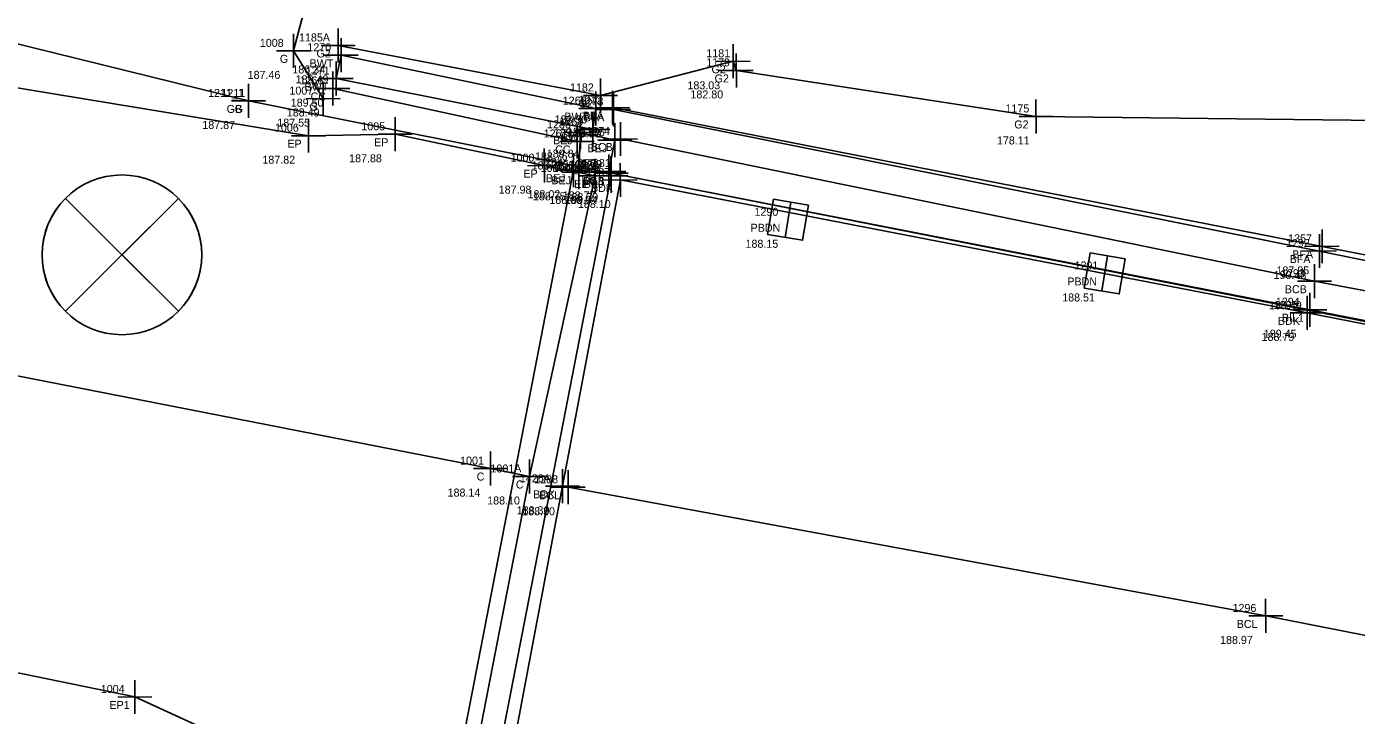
# Model space of a CAD drawing. Extents: x 1157913 to 1159198, y 600595 to 601244.
# Drawn here: x 1158460.89 to 1158510.75, y 600928.57 to 600954.39 of the extents above; entities that cross this region are included whole.
import ezdxf

# ---------------------------------------------------------------- set-up
doc = ezdxf.new("R2010")
doc.units = 0
for name, color, linetype in [('Default', 7, 'Continuous'), ('S_BoringLocation_AsDrilled', 7, 'Continuous'), ('S_Bridge_Centerline', 7, 'Continuous'), ('S_Bridge_Curb', 7, 'Continuous'), ('S_Bridge_Deck', 7, 'Continuous'), ('S_Bridge_Downspout', 7, 'Continuous'), ('S_Bridge_ExpansionJoint', 7, 'Continuous'), ('S_Bridge_Fascia', 7, 'Continuous'), ('S_Bridge_Rail', 7, 'Continuous'), ('S_Bridge_Wingwall', 7, 'Continuous'), ('S_Curb_Type_2', 7, 'Continuous'), ('S_Field_Code', 7, 'Continuous'), ('S_Ground_Elevation', 7, 'Continuous'), ('S_Ground_LevelString', 7, 'Continuous'), ('S_Guardrail_Beam', 7, 'Continuous'), ('S_Point_Elevation', 7, 'Continuous'), ('S_Point_Name', 7, 'Continuous'), ('S_Roadway_Centerline', 7, 'Continuous'), ('S_Roadway_Edge_Pavement', 7, 'Continuous'), ('S_Survey_Shot', 7, 'Continuous')]:
    doc.layers.add(name, color=color, linetype=linetype)

msp = doc.modelspace()

# ---------------------------------------------------------------- linework, layer by layer
at = {"layer": 'Default'}
for p, q in [((1158489.439, 600947.15), (1158489.439, 600947.15)), ((1158501.314, 600945.137), (1158501.314, 600945.137))]:
    msp.add_line(p, q, dxfattribs=at)
at = {"layer": 'S_BoringLocation_AsDrilled'}
for p, q in [((1158462.347, 600947.953), (1158466.581, 600943.719)), ((1158462.347, 600943.719), (1158466.581, 600947.953))]:
    msp.add_line(p, q, dxfattribs=at)
for points in [[(1158462.347, 600943.719), (1158464.464, 600945.836), (1158462.347, 600947.953)], [(1158466.581, 600947.953), (1158464.464, 600945.836), (1158466.581, 600943.719)]]:
    msp.add_lwpolyline(points, dxfattribs=at)
msp.add_circle((1158464.464, 600945.836), 2.994, dxfattribs=at)
for start, end in [(135, 225), (315, 45)]:
    msp.add_arc((1158464.464, 600945.836), 2.994, start, end, dxfattribs=at)
at = {"layer": 'S_Bridge_Centerline'}
msp.add_lwpolyline([(1158481.195, 600937.121), (1158507.351, 600932.296), (1158531.006, 600927.652), (1158554.323, 600923.112), (1158577.507, 600918.68), (1158601.407, 600914.027), (1158625.013, 600909.477), (1158647.737, 600904.925), (1158672.228, 600900.301), (1158696.593, 600895.817), (1158720.484, 600890.638)], dxfattribs=at)
at = {"layer": 'S_Bridge_Curb'}
msp.add_lwpolyline([(1158483.161, 600950.18), (1158509.184, 600944.847), (1158532.763, 600940.379), (1158556.45, 600935.563), (1158579.829, 600931.057), (1158603.376, 600926.445), (1158626.911, 600921.776), (1158650.768, 600917.187), (1158674.064, 600912.392), (1158697.671, 600908.06), (1158723.302, 600902.985)], dxfattribs=at)
at = {"layer": 'S_Bridge_Deck'}
msp.add_lwpolyline([(1158483.154, 600948.642), (1158508.91, 600943.661), (1158532.625, 600939.025), (1158556.015, 600934.45), (1158579.602, 600929.788), (1158603.216, 600925.172), (1158626.871, 600920.52), (1158650.274, 600915.846), (1158673.938, 600911.396), (1158697.587, 600906.778), (1158722.887, 600901.626), (1158720.511, 600890.631), (1158717.86, 600878.361), (1158692.562, 600883.367), (1158669.405, 600887.913), (1158645.122, 600892.525), (1158622.108, 600897.299), (1158598.216, 600901.842), (1158574.819, 600906.519), (1158551.011, 600911.144), (1158527.523, 600915.567), (1158503.608, 600920.228), (1158478.738, 600925.244), (1158480.987, 600937.158)], close=True, dxfattribs=at)
at = {"layer": 'S_Bridge_Downspout'}
for p, q in [((1158489.549, 600947.807), (1158489.329, 600946.492)), ((1158501.424, 600945.795), (1158501.204, 600944.48))]:
    msp.add_line(p, q, dxfattribs=at)
for points in [[(1158488.891, 600947.917), (1158490.207, 600947.698), (1158489.987, 600946.382), (1158488.672, 600946.602)], [(1158500.766, 600945.905), (1158502.081, 600945.685), (1158501.862, 600944.37), (1158500.547, 600944.59)]]:
    msp.add_lwpolyline(points, close=True, dxfattribs=at)
at = {"layer": 'S_Bridge_ExpansionJoint'}
msp.add_lwpolyline([(1158482.951, 600950.133), (1158482.722, 600948.965), (1158482.812, 600948.797), (1158478.267, 600925.445), (1158478.173, 600925.283), (1158477.852, 600924.467), (1158476.579, 600924.608), (1158476.87, 600925.538), (1158476.863, 600925.631), (1158481.393, 600949.008), (1158481.599, 600948.931), (1158481.661, 600950.428)], close=True, dxfattribs=at)
at = {"layer": 'S_Bridge_Fascia'}
msp.add_lwpolyline([(1158482.861, 600951.354), (1158482.898, 600951.287), (1158509.367, 600945.979), (1158532.925, 600941.176), (1158556.366, 600936.562), (1158579.862, 600931.952), (1158603.5, 600927.221), (1158627.041, 600922.676), (1158650.576, 600918.007), (1158674.159, 600913.359), (1158697.787, 600908.797), (1158724.39, 600903.681), (1158724.298, 600904.075), (1158697.887, 600909.28), (1158674.374, 600913.874), (1158650.514, 600918.558), (1158627.158, 600923.073), (1158603.563, 600927.819), (1158579.96, 600932.392), (1158556.434, 600937.017), (1158532.882, 600941.581), (1158509.466, 600946.154)], close=True, dxfattribs=at)
at = {"layer": 'S_Bridge_Rail'}
msp.add_lwpolyline([(1158482.805, 600948.902), (1158509.002, 600943.778), (1158532.726, 600939.143), (1158579.85, 600929.84), (1158603.334, 600925.337), (1158626.819, 600920.746), (1158650.464, 600916.056), (1158674.206, 600911.454), (1158697.827, 600906.811), (1158723.142, 600901.903)], dxfattribs=at)
at = {"layer": 'S_Bridge_Wingwall'}
msp.add_lwpolyline([(1158482.119, 600950.531), (1158482.238, 600951.319), (1158472.688, 600953.318), (1158472.501, 600952.443)], close=True, dxfattribs=at)
at = {"layer": 'S_Curb_Type_2'}
msp.add_lwpolyline([(1158472.368, 600952.074), (1158481.537, 600950.087)], dxfattribs=at)
at = {"layer": 'S_Ground_Elevation'}
for points in [[(1158472.015, 600951.692), (1158470.903, 600953.484), (1158471.497, 600955.775), (1158438.857, 600962.856), (1158401.09, 600969.759), (1158355.506, 600978.983), (1158309.086, 600988.559), (1158285.714, 600993.001), (1158274.891, 600997.675), (1158269.917, 601000.901)], [(1158273.349, 600992.479), (1158301.688, 600987.714), (1158337.49, 600979.594), (1158372.463, 600972.765), (1158424.594, 600962.151), (1158447.246, 600957.035), (1158469.207, 600951.606)], [(1158513.787, 600950.853), (1158498.739, 600951.025), (1158487.502, 600952.75), (1158487.388, 600953.092), (1158482.406, 600951.812), (1158472.577, 600953.687)]]:
    msp.add_lwpolyline(points, dxfattribs=at)
at = {"layer": 'S_Ground_LevelString'}
msp.add_line((1158482.21, 600948.796), (1158482.21, 600948.796), dxfattribs=at)
for points in [[(1158482.21, 600948.796), (1158479.75, 600937.525)], [(1158477.417, 600925.559), (1158479.75, 600937.525)]]:
    msp.add_lwpolyline(points, dxfattribs=at)
at = {"layer": 'S_Guardrail_Beam'}
msp.add_lwpolyline([(1158300.685, 600990.749), (1158313.178, 600986.765), (1158323.044, 600983.483), (1158337.49, 600979.594), (1158372.463, 600972.765), (1158424.594, 600962.151), (1158447.246, 600957.035), (1158469.207, 600951.606), (1158482.805, 600948.902), (1158556.266, 600934.455)], dxfattribs=at)
at = {"layer": 'S_Roadway_Centerline'}
msp.add_lwpolyline([(1158479.75, 600937.525), (1158478.282, 600937.822), (1158436.668, 600945.983), (1158396.56, 600953.994), (1158354.467, 600962.235), (1158305.826, 600972.373), (1158264.305, 600980.659), (1158241.502, 600985.057), (1158213.717, 600990.543), (1158173.691, 600998.161), (1158140.3, 601004.996), (1158100.103, 601012.585), (1158058.41, 601021.086), (1158006.872, 601031.132), (1157981.56, 601036.209), (1157941.48, 601043.319), (1157939.696, 601043.817)], dxfattribs=at)
at = {"layer": 'S_Roadway_Edge_Pavement'}
for points in [[(1158482.21, 600948.796), (1158480.303, 600949.181), (1158474.708, 600950.356), (1158471.456, 600950.303), (1158438.531, 600955.721), (1158399.619, 600963.989), (1158355.02, 600972.94), (1158308.672, 600982.448), (1158275.006, 600989.351), (1158238.064, 600996.902), (1158217.026, 601000.576), (1158187.54, 601006.694), (1158142.453, 601015.564), (1158101.816, 601023.851), (1158061.148, 601031.765), (1158007.725, 601042.002), (1157989.546, 601045.447), (1157985.531, 601046.098), (1157938.913, 601055.56)], [(1158477.417, 600925.559), (1158475.969, 600925.8), (1158470.307, 600926.811), (1158464.953, 600929.258), (1158434.419, 600935.565), (1158394.467, 600943.733), (1158353.382, 600952.235), (1158303.702, 600962.318), (1158261.836, 600970.726), (1158252.612, 600972.631), (1158210.037, 600978.929), (1158172.668, 600988.59), (1158138.81, 600995.015), (1158098.517, 601002.533), (1158056.874, 601010.931), (1158005.398, 601020.726), (1157975.101, 601026.613), (1157952.322, 601030.415), (1157945.74, 601032.454), (1157914.88, 601038.54)]]:
    msp.add_lwpolyline(points, dxfattribs=at)
at = {"layer": 'S_Survey_Shot'}
for p, q in [((1158470.904, 600952.848), (1158470.902, 600954.12)), ((1158472.578, 600953.051), (1158472.575, 600954.324)), ((1158472.689, 600952.682), (1158472.686, 600953.954)), ((1158470.267, 600953.483), (1158471.539, 600953.485)), ((1158470.903, 600953.484), (1158470.903, 600953.484)), ((1158471.94, 600953.686), (1158473.213, 600953.689)), ((1158472.577, 600953.687), (1158472.577, 600953.687)), ((1158487.389, 600952.456), (1158487.387, 600953.729)), ((1158487.503, 600952.114), (1158487.5, 600953.387)), ((1158472.051, 600953.317), (1158473.324, 600953.319)), ((1158472.502, 600951.807), (1158472.499, 600953.079)), ((1158472.688, 600953.318), (1158472.688, 600953.318)), ((1158486.752, 600953.091), (1158488.024, 600953.094)), ((1158487.388, 600953.092), (1158487.388, 600953.092)), ((1158471.864, 600952.442), (1158473.137, 600952.444)), ((1158472.37, 600951.438), (1158472.367, 600952.71)), ((1158472.501, 600952.443), (1158472.501, 600952.443)), ((1158482.408, 600951.176), (1158482.405, 600952.448)), ((1158486.865, 600952.749), (1158488.138, 600952.752)), ((1158487.502, 600952.75), (1158487.502, 600952.75)), ((1158469.208, 600950.97), (1158469.205, 600952.242)), ((1158469.208, 600950.97), (1158469.205, 600952.242)), ((1158471.732, 600952.073), (1158473.005, 600952.075)), ((1158472.016, 600951.055), (1158472.013, 600952.328)), ((1158472.368, 600952.074), (1158472.368, 600952.074)), ((1158482.239, 600950.682), (1158482.237, 600951.955)), ((1158482.863, 600950.717), (1158482.86, 600951.99)), ((1158482.899, 600950.651), (1158482.896, 600951.923)), ((1158468.57, 600951.605), (1158469.843, 600951.607)), ((1158468.57, 600951.605), (1158469.843, 600951.607)), ((1158469.207, 600951.606), (1158469.207, 600951.606)), ((1158469.207, 600951.606), (1158469.207, 600951.606)), ((1158471.379, 600951.69), (1158472.651, 600951.693)), ((1158472.015, 600951.692), (1158472.015, 600951.692)), ((1158481.77, 600951.811), (1158483.042, 600951.813)), ((1158482.225, 600951.352), (1158483.497, 600951.355)), ((1158482.406, 600951.812), (1158482.406, 600951.812)), ((1158482.861, 600951.354), (1158482.861, 600951.354)), ((1158498.741, 600950.389), (1158498.738, 600951.662)), ((1158471.457, 600949.667), (1158471.455, 600950.939)), ((1158474.709, 600949.72), (1158474.707, 600950.992)), ((1158481.602, 600951.317), (1158482.874, 600951.32)), ((1158481.662, 600949.792), (1158481.66, 600951.064)), ((1158482.12, 600949.895), (1158482.118, 600951.168)), ((1158482.238, 600951.319), (1158482.238, 600951.319)), ((1158482.261, 600951.286), (1158483.534, 600951.288)), ((1158482.898, 600951.287), (1158482.898, 600951.287)), ((1158498.103, 600951.024), (1158499.376, 600951.027)), ((1158498.739, 600951.025), (1158498.739, 600951.025)), ((1158474.072, 600950.355), (1158475.344, 600950.357)), ((1158474.708, 600950.356), (1158474.708, 600950.356)), ((1158481.025, 600950.427), (1158482.297, 600950.43)), ((1158481.483, 600950.53), (1158482.755, 600950.533)), ((1158481.538, 600949.451), (1158481.536, 600950.723)), ((1158481.661, 600950.428), (1158481.661, 600950.428)), ((1158482.119, 600950.531), (1158482.119, 600950.531)), ((1158482.952, 600949.497), (1158482.95, 600950.77)), ((1158483.162, 600949.544), (1158483.16, 600950.816)), ((1158470.82, 600950.301), (1158472.092, 600950.304)), ((1158471.456, 600950.303), (1158471.456, 600950.303)), ((1158480.901, 600950.086), (1158482.173, 600950.088)), ((1158481.537, 600950.087), (1158481.537, 600950.087)), ((1158482.315, 600950.132), (1158483.587, 600950.135)), ((1158482.525, 600950.179), (1158483.797, 600950.181)), ((1158482.951, 600950.133), (1158482.951, 600950.133)), ((1158483.161, 600950.18), (1158483.161, 600950.18)), ((1158480.305, 600948.544), (1158480.302, 600949.817)), ((1158481.395, 600948.371), (1158481.392, 600949.644)), ((1158481.6, 600948.294), (1158481.597, 600949.567)), ((1158482.211, 600948.159), (1158482.209, 600949.432)), ((1158482.211, 600948.159), (1158482.209, 600949.432)), ((1158482.723, 600948.328), (1158482.72, 600949.601)), ((1158482.806, 600948.266), (1158482.803, 600949.538)), ((1158482.806, 600948.266), (1158482.803, 600949.538)), ((1158482.813, 600948.161), (1158482.81, 600949.433)), ((1158479.667, 600949.179), (1158480.939, 600949.182)), ((1158480.303, 600949.181), (1158480.303, 600949.181)), ((1158480.757, 600949.006), (1158482.03, 600949.009)), ((1158480.962, 600948.929), (1158482.235, 600948.932)), ((1158481.393, 600949.008), (1158481.393, 600949.008)), ((1158481.599, 600948.931), (1158481.599, 600948.931)), ((1158482.085, 600948.963), (1158483.358, 600948.966)), ((1158482.169, 600948.901), (1158483.441, 600948.903)), ((1158482.169, 600948.901), (1158483.441, 600948.903)), ((1158482.722, 600948.965), (1158482.722, 600948.965)), ((1158482.805, 600948.902), (1158482.805, 600948.902)), ((1158482.805, 600948.902), (1158482.805, 600948.902)), ((1158483.155, 600948.006), (1158483.152, 600949.278)), ((1158481.574, 600948.794), (1158482.846, 600948.797)), ((1158481.574, 600948.794), (1158482.846, 600948.797)), ((1158482.176, 600948.796), (1158483.448, 600948.798)), ((1158482.21, 600948.796), (1158482.21, 600948.796)), ((1158482.21, 600948.796), (1158482.21, 600948.796)), ((1158482.517, 600948.641), (1158483.79, 600948.643)), ((1158482.812, 600948.797), (1158482.812, 600948.797)), ((1158483.154, 600948.642), (1158483.154, 600948.642)), ((1158509.368, 600945.343), (1158509.366, 600946.615)), ((1158509.468, 600945.518), (1158509.465, 600946.791)), ((1158508.731, 600945.977), (1158510.003, 600945.98)), ((1158508.83, 600946.153), (1158510.103, 600946.156)), ((1158509.367, 600945.979), (1158509.367, 600945.979)), ((1158509.466, 600946.154), (1158509.466, 600946.154)), ((1158509.185, 600944.211), (1158509.182, 600945.483)), ((1158508.547, 600944.846), (1158509.82, 600944.848)), ((1158509.003, 600943.141), (1158509.001, 600944.414)), ((1158509.184, 600944.847), (1158509.184, 600944.847)), ((1158508.911, 600943.025), (1158508.909, 600944.297)), ((1158508.274, 600943.66), (1158509.546, 600943.663)), ((1158508.366, 600943.776), (1158509.638, 600943.779)), ((1158508.91, 600943.661), (1158508.91, 600943.661)), ((1158509.002, 600943.778), (1158509.002, 600943.778)), ((1158478.283, 600937.185), (1158478.281, 600938.458)), ((1158479.751, 600936.889), (1158479.749, 600938.162)), ((1158477.646, 600937.82), (1158478.918, 600937.823)), ((1158478.282, 600937.822), (1158478.282, 600937.822)), ((1158479.114, 600937.524), (1158480.386, 600937.527)), ((1158479.75, 600937.525), (1158479.75, 600937.525)), ((1158480.988, 600936.522), (1158480.985, 600937.794)), ((1158481.196, 600936.485), (1158481.193, 600937.758)), ((1158480.35, 600937.157), (1158481.623, 600937.159)), ((1158480.558, 600937.12), (1158481.831, 600937.123)), ((1158480.987, 600937.158), (1158480.987, 600937.158)), ((1158481.195, 600937.121), (1158481.195, 600937.121)), ((1158507.353, 600931.66), (1158507.35, 600932.932)), ((1158506.715, 600932.294), (1158507.988, 600932.297)), ((1158507.351, 600932.296), (1158507.351, 600932.296)), ((1158464.955, 600928.621), (1158464.952, 600929.894)), ((1158464.317, 600929.256), (1158465.589, 600929.259)), ((1158464.953, 600929.258), (1158464.953, 600929.258))]:
    msp.add_line(p, q, dxfattribs=at)

# ---------------------------------------------------------------- texts
at = {"layer": 'S_Field_Code'}
for s, p in [('G', (1158470.388, 600953.034)), ('G2', (1158471.762, 600953.237)), ('BWT', (1158471.502, 600952.868)), ('G2', (1158486.573, 600952.642)), ('G2', (1158486.687, 600952.3)), ('BWT', (1158471.315, 600951.993)), ('CC', (1158471.539, 600951.624)), ('GB', (1158468.392, 600951.156)), ('G', (1158468.692, 600951.156)), ('G', (1158471.5, 600951.242)), ('G2', (1158481.591, 600951.362)), ('BWT', (1158481.052, 600950.869)), ('BFA', (1158481.744, 600950.904)), ('BFA', (1158481.781, 600950.837)), ('G2', (1158497.924, 600950.575)), ('BWT', (1158480.933, 600950.081)), ('EP', (1158470.669, 600949.853)), ('EP', (1158473.921, 600949.906)), ('BEJ', (1158480.631, 600949.978)), ('CC', (1158480.708, 600949.637)), ('BEJ', (1158481.921, 600949.683)), ('BCB', (1158482.046, 600949.73)), ('EP', (1158479.517, 600948.731)), ('BEJ', (1158480.364, 600948.558)), ('BEJ', (1158480.569, 600948.481)), ('EP', (1158481.423, 600948.346)), ('BEJ', (1158481.692, 600948.515)), ('L', (1158481.737, 600948.346)), ('BIL1', (1158481.763, 600948.452)), ('BEJ', (1158481.782, 600948.347)), ('GB', (1158481.99, 600948.452)), ('BDK', (1158482.053, 600948.192)), ('PBDN', (1158488.038, 600946.7)), ('BFA', (1158508.349, 600945.704)), ('BFA', (1158508.25, 600945.529)), ('PBDN', (1158499.913, 600944.687)), ('BCB', (1158508.069, 600944.397)), ('BDK', (1158507.809, 600943.211)), ('BIL1', (1158507.96, 600943.328)), ('C', (1158477.767, 600937.372)), ('C', (1158479.235, 600937.075)), ('BDK', (1158479.886, 600936.708)), ('BCL', (1158480.108, 600936.671)), ('BCL', (1158506.265, 600931.846)), ('EP1', (1158463.997, 600928.808))]:
    msp.add_text(s, height=0.3, dxfattribs=at).set_placement(p)
at = {"layer": 'S_Point_Elevation'}
for s, p in [('186.34', (1158470.855, 600952.637)), ('187.46', (1158469.179, 600952.434)), ('189.49', (1158470.98, 600952.268)), ('183.03', (1158485.669, 600952.042)), ('182.80', (1158485.782, 600951.7)), ('189.50', (1158470.795, 600951.393)), ('187.87', (1158467.48, 600950.556)), ('187.87', (1158467.48, 600950.556)), ('187.55', (1158470.291, 600950.642)), ('188.49', (1158470.647, 600951.024)), ('183.50', (1158480.687, 600950.762)), ('189.81', (1158480.66, 600950.269)), ('187.39', (1158481.151, 600950.304)), ('189.83', (1158481.19, 600950.237)), ('178.11', (1158497.275, 600949.975)), ('187.82', (1158469.732, 600949.253)), ('187.88', (1158472.984, 600949.306)), ('188.76', (1158479.951, 600949.378)), ('189.84', (1158480.397, 600949.481)), ('188.79', (1158481.241, 600949.083)), ('188.81', (1158481.569, 600949.13)), ('188.76', (1158479.827, 600949.037)), ('187.98', (1158478.593, 600948.131)), ('188.02', (1158479.674, 600947.958)), ('188.75', (1158479.875, 600947.881)), ('188.00', (1158480.493, 600947.746)), ('188.00', (1158480.493, 600947.746)), ('188.77', (1158480.995, 600947.915)), ('188.04', (1158481.078, 600947.747)), ('188.79', (1158481.095, 600947.852)), ('188.79', (1158481.095, 600947.852)), ('188.10', (1158481.564, 600947.592)), ('188.15', (1158487.847, 600946.1)), ('187.95', (1158507.757, 600945.104)), ('190.48', (1158507.648, 600944.929)), ('188.51', (1158499.722, 600944.087)), ('189.49', (1158507.476, 600943.797)), ('188.79', (1158507.2, 600942.611)), ('189.45', (1158507.28, 600942.728)), ('188.14', (1158476.676, 600936.772)), ('188.10', (1158478.161, 600936.475)), ('188.30', (1158479.267, 600936.108)), ('188.30', (1158479.475, 600936.071)), ('188.97', (1158505.641, 600931.246))]:
    msp.add_text(s, height=0.3, dxfattribs=at).set_placement(p)
at = {"layer": 'S_Point_Name'}
for s, p in [('1008', (1158469.637, 600953.634)), ('1185A', (1158471.105, 600953.837)), ('1270', (1158471.417, 600953.468)), ('1181', (1158486.377, 600953.242)), ('1271', (1158471.358, 600952.593)), ('1179', (1158486.373, 600952.9)), ('1266', (1158471.126, 600952.224)), ('1211_1', (1158467.697, 600951.756)), ('1211', (1158468.196, 600951.756)), ('1007', (1158470.746, 600951.842)), ('1182', (1158481.265, 600951.962)), ('1269', (1158480.996, 600951.469)), ('1272', (1158481.588, 600951.504)), ('1273', (1158481.625, 600951.437)), ('1175', (1158497.596, 600951.175)), ('1286', (1158480.404, 600950.578)), ('1268', (1158480.863, 600950.681)), ('1006', (1158470.204, 600950.453)), ('1005', (1158473.442, 600950.506)), ('1267', (1158480.278, 600950.237)), ('1275', (1158481.678, 600950.283)), ('1274', (1158481.874, 600950.33)), ('1000', (1158479.04, 600949.331)), ('1284', (1158480.108, 600949.158)), ('1285', (1158480.328, 600949.081)), ('1289A_1', (1158480.764, 600949.052)), ('1289A', (1158481.218, 600949.052)), ('1276', (1158481.463, 600949.115)), ('1000A_1', (1158480.162, 600948.946)), ('1000A', (1158480.616, 600948.946)), ('1277', (1158481.536, 600948.947)), ('1287', (1158481.88, 600948.792)), ('1290', (1158488.185, 600947.3)), ('1292', (1158508.11, 600946.129)), ('1357', (1158508.193, 600946.304)), ('1291', (1158500.187, 600945.287)), ('1293', (1158507.927, 600944.997)), ('1295', (1158507.654, 600943.811)), ('1294', (1158507.731, 600943.928)), ('1001', (1158477.146, 600937.972)), ('1001A', (1158478.283, 600937.675)), ('1426A', (1158479.385, 600937.308)), ('1288', (1158479.924, 600937.271)), ('1296', (1158506.109, 600932.446)), ('1004', (1158463.673, 600929.408))]:
    msp.add_text(s, height=0.3, dxfattribs=at).set_placement(p)

doc.saveas('drawing.dxf')
